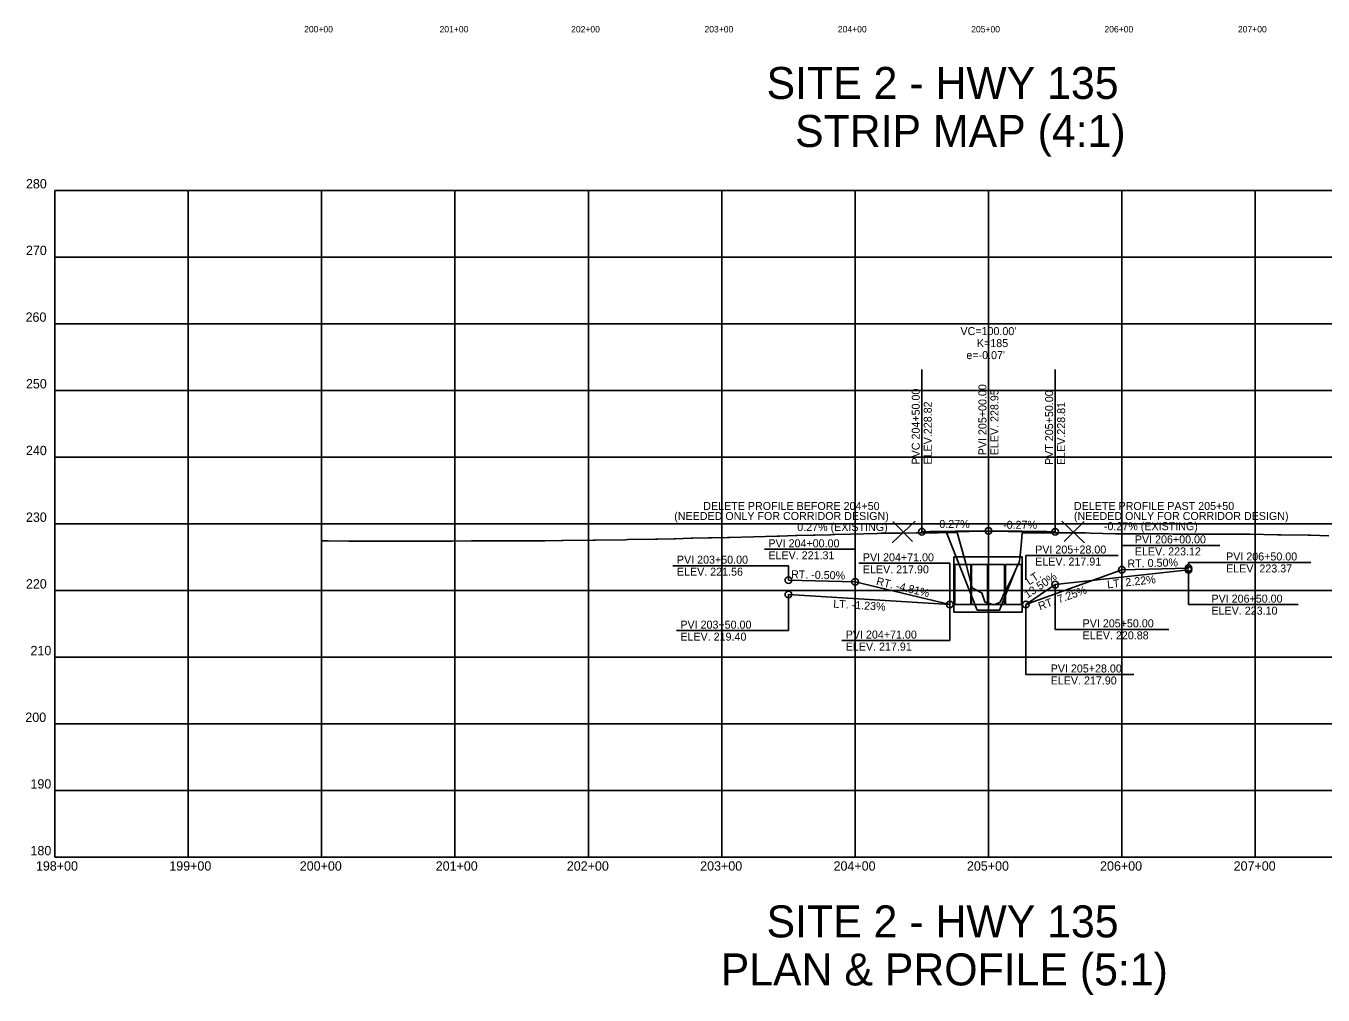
# Model space of a CAD drawing. Extents: x 1801553 to 1803097, y 521610 to 523048.
# Drawn here: x 1801553 to 1802526, y 521610 to 522336 of the extents above; entities that cross this region are included whole.
import ezdxf

# ---------------------------------------------------------------- set-up
doc = ezdxf.new("R2010")
doc.units = 0
for name, color, linetype in [('Default', 7, 'Continuous'), ('R_Axis', 7, 'Continuous'), ('R_Axis Annot', 7, 'Continuous'), ('R_Concrete', 7, 'Continuous'), ('R_Exist Surface', 7, 'Continuous'), ('R_Grid', 7, 'Continuous'), ('R_No Plot', 7, 'Continuous'), ('R_Vert Alg', 7, 'Continuous'), ('R_Vert Alg Annot', 7, 'Continuous')]:
    doc.layers.add(name, color=color, linetype=linetype)

msp = doc.modelspace()

# ---------------------------------------------------------------- linework, layer by layer
at = {"layer": 'R_Axis'}
for q in [(1801574.68, 522212.85), (1803074.68, 521712.85)]:
    msp.add_line((1801574.68, 521712.85), q, dxfattribs=at)
at = {"layer": 'R_Concrete'}
for p, q in [((1802248.83, 521938.21), (1802248.83, 521896.54)), ((1802248.83, 521938.21), (1802300, 521938.21)), ((1802249.42, 521932.37), (1802261.42, 521932.37)), ((1802249.42, 521932.37), (1802249.42, 521902.37)), ((1802261.42, 521932.37), (1802261.42, 521902.37)), ((1802262.08, 521932.37), (1802262.08, 521902.37)), ((1802262.08, 521932.37), (1802274.08, 521932.37)), ((1802274.08, 521932.37), (1802274.08, 521902.37)), ((1802274.75, 521932.37), (1802274.75, 521902.37)), ((1802274.75, 521932.37), (1802286.75, 521932.37)), ((1802286.75, 521932.37), (1802286.75, 521902.37)), ((1802287.42, 521932.37), (1802287.42, 521902.37)), ((1802287.42, 521932.37), (1802299.42, 521932.37)), ((1802299.42, 521932.37), (1802299.42, 521902.37)), ((1802300, 521938.21), (1802300, 521896.54)), ((1802261.42, 521902.37), (1802249.42, 521902.37)), ((1802274.08, 521902.37), (1802262.08, 521902.37)), ((1802286.75, 521902.37), (1802274.75, 521902.37)), ((1802299.42, 521902.37), (1802287.42, 521902.37)), ((1802300, 521896.54), (1802248.83, 521896.54))]:
    msp.add_line(p, q, dxfattribs=at)
at = {"layer": 'R_Exist Surface'}
msp.add_lwpolyline([(1801774.68, 521949.99), (1801779.53, 521949.99), (1801779.55, 521949.99), (1801795.04, 521949.94), (1801795.2, 521949.94), (1801795.36, 521949.94), (1801810.85, 521949.9), (1801811.16, 521949.9), (1801826.5, 521949.86), (1801826.96, 521949.86), (1801842.14, 521949.82), (1801842.73, 521949.82), (1801857.1, 521949.88), (1801857.73, 521949.88), (1801872.07, 521949.94), (1801872.73, 521949.94), (1801887.03, 521950), (1801887.73, 521950), (1801902, 521950.06), (1801902.65, 521950.06), (1801915.41, 521950.11), (1801916.11, 521950.11), (1801928.83, 521950.16), (1801929.57, 521950.17), (1801942.24, 521950.22), (1801954.83, 521950.27), (1801955.65, 521950.27), (1801978.39, 521950.61), (1801980.11, 521950.63), (1802002.64, 521950.97), (1802004.56, 521950.99), (1802025.05, 521951.38), (1802026.71, 521951.4), (1802038.77, 521951.69), (1802039.78, 521951.72), (1802051.81, 521952), (1802052.84, 521952.03), (1802064.84, 521952.31), (1802065.9, 521952.34), (1802066.97, 521952.37), (1802078.97, 521952.65), (1802080.66, 521952.69), (1802098.53, 521953.17), (1802116.39, 521953.64), (1802118.1, 521953.68), (1802130.1, 521954.01), (1802131.39, 521954.04), (1802143.23, 521954.37), (1802144.68, 521954.4), (1802156.37, 521954.72), (1802157.97, 521954.76), (1802159.59, 521954.8), (1802171.25, 521955.12), (1802191.24, 521955.66), (1802194.31, 521955.77), (1802206.52, 521955.9), (1802208.52, 521955.92), (1802220.57, 521956.05), (1802222.73, 521956.08), (1802234.62, 521956.2), (1802236.95, 521956.23), (1802248.67, 521956.35), (1802251.16, 521956.38), (1802258.17, 521931.27), (1802262.44, 521914.86), (1802268.58, 521911.7), (1802269.81, 521911.01), (1802272.01, 521904.44), (1802272.23, 521904.08), (1802277.68, 521902.34), (1802278.55, 521902.15), (1802279.41, 521902.43), (1802283.57, 521904.18), (1802285.34, 521907.84), (1802285.55, 521908.76), (1802287.93, 521913.25), (1802292.45, 521922.57), (1802296.87, 521932.49), (1802297.76, 521933.98), (1802298.18, 521936.95), (1802299.13, 521946.69), (1802300.08, 521956.13), (1802303.92, 521956.13), (1802323.8, 521956.07), (1802327.44, 521956.07), (1802347.53, 521956.02), (1802350.99, 521955.94), (1802369.84, 521955.41), (1802387.55, 521955.33), (1802391.57, 521955.32), (1802409.64, 521955.24), (1802413.16, 521955.22), (1802425.23, 521955.19), (1802428.49, 521955.16), (1802440.59, 521955.13), (1802452.86, 521955.1), (1802455.82, 521955.08), (1802468.11, 521955.05), (1802470.73, 521955.02), (1802491.31, 521954.71), (1802494, 521954.67), (1802514.51, 521954.37), (1802516.38, 521954.32), (1802529.8, 521953.97)], dxfattribs=at)
at = {"layer": 'R_Grid'}
for p, q in [((1801574.68, 522212.85), (1803074.68, 522212.85)), ((1801674.68, 521712.85), (1801674.68, 522212.85)), ((1801774.68, 521712.85), (1801774.68, 522212.85)), ((1801874.68, 521712.85), (1801874.68, 522212.85)), ((1801974.68, 521712.85), (1801974.68, 522212.85)), ((1802074.68, 521712.85), (1802074.68, 522212.85)), ((1802174.68, 521712.85), (1802174.68, 522212.85)), ((1802274.68, 521712.85), (1802274.68, 522212.85)), ((1802374.68, 521712.85), (1802374.68, 522212.85)), ((1802474.68, 521712.85), (1802474.68, 522212.85)), ((1801574.68, 522162.85), (1803074.68, 522162.85)), ((1801574.68, 522112.85), (1803074.68, 522112.85)), ((1801574.68, 522112.85), (1803074.68, 522112.85)), ((1801574.68, 522062.85), (1803074.68, 522062.85)), ((1801574.68, 522012.85), (1803074.68, 522012.85)), ((1801574.68, 521962.85), (1803074.68, 521962.85)), ((1801574.68, 521912.85), (1803074.68, 521912.85)), ((1801574.68, 521862.85), (1803074.68, 521862.85)), ((1801574.68, 521812.85), (1803074.68, 521812.85)), ((1801574.68, 521762.85), (1803074.68, 521762.85))]:
    msp.add_line(p, q, dxfattribs=at)
at = {"layer": 'R_No Plot'}
for p, q in [((1802219.65, 521964.89), (1802202.55, 521948.56)), ((1802202.98, 521964.64), (1802217.85, 521949.58)), ((1802329.71, 521964.89), (1802346.81, 521948.56)), ((1802346.38, 521964.64), (1802331.51, 521949.58))]:
    msp.add_line(p, q, dxfattribs=at)
msp.add_lwpolyline([(1802243.12, 521956.29), (1802266.35, 521898.21), (1802267.85, 521898.21), (1802281.51, 521898.21), (1802283.01, 521898.21), (1802295.46, 521929.33)], dxfattribs=at)
at = {"layer": 'R_Vert Alg'}
for p, q in [((1802249.68, 521957.26), (1802274.68, 521957.6)), ((1802274.68, 521957.6), (1802299.68, 521957.26)), ((1802124.68, 521920.66), (1802174.68, 521919.41)), ((1802302.68, 521902.35), (1802374.68, 521928.45)), ((1802324.68, 521917.25), (1802424.68, 521928.35)), ((1802374.68, 521928.45), (1802424.68, 521929.7)), ((1802174.68, 521919.41), (1802245.68, 521902.35)), ((1802302.68, 521902.4), (1802324.68, 521917.25)), ((1802124.68, 521909.82), (1802245.68, 521902.4))]:
    msp.add_line(p, q, dxfattribs=at)
msp.add_lwpolyline([(1802224.68, 521956.93), (1802226.76, 521956.96), (1802228.85, 521956.98), (1802230.93, 521957.01), (1802233.01, 521957.03), (1802235.1, 521957.05), (1802237.18, 521957.08), (1802239.26, 521957.1), (1802241.35, 521957.11), (1802243.43, 521957.13), (1802245.51, 521957.15), (1802247.6, 521957.16), (1802249.68, 521957.18), (1802251.76, 521957.19), (1802253.85, 521957.2), (1802255.93, 521957.22), (1802258.01, 521957.22), (1802260.1, 521957.23), (1802262.18, 521957.24), (1802264.26, 521957.25), (1802266.35, 521957.25), (1802268.43, 521957.26), (1802270.51, 521957.26), (1802272.6, 521957.26), (1802276.76, 521957.26), (1802278.85, 521957.26), (1802280.93, 521957.25), (1802283.01, 521957.25), (1802285.1, 521957.24), (1802287.18, 521957.24), (1802289.26, 521957.23), (1802291.35, 521957.22), (1802293.43, 521957.21), (1802295.51, 521957.2), (1802297.6, 521957.19), (1802299.68, 521957.17), (1802301.76, 521957.16), (1802303.85, 521957.14), (1802305.93, 521957.12), (1802308.01, 521957.11), (1802310.1, 521957.09), (1802312.18, 521957.07), (1802314.26, 521957.04), (1802316.35, 521957.02), (1802318.43, 521957), (1802320.51, 521956.97), (1802322.6, 521956.94), (1802324.68, 521956.92)], dxfattribs=at)
at = {"layer": 'R_Vert Alg Annot'}
for p, q in [((1802224.68, 522078.68), (1802224.68, 521956.93)), ((1802274.68, 521957.6), (1802274.68, 522078.68)), ((1802324.68, 522078.68), (1802324.68, 521956.92)), ((1802106.68, 521943.75), (1802174.68, 521943.75)), ((1802174.68, 521919.41), (1802174.68, 521943.75)), ((1802374.68, 521928.45), (1802374.68, 521946.68)), ((1802374.68, 521946.68), (1802448.09, 521946.68)), ((1802038.1, 521931.48), (1802124.68, 521931.48)), ((1802124.68, 521920.66), (1802124.68, 521931.48)), ((1802177.52, 521933.24), (1802245.68, 521933.24)), ((1802245.68, 521902.4), (1802245.68, 521933.24)), ((1802302.68, 521939.09), (1802372.05, 521939.09)), ((1802302.68, 521920.86), (1802302.68, 521939.09)), ((1802424.68, 521929.7), (1802424.68, 521933.89)), ((1802424.68, 521933.89), (1802516.5, 521933.89)), ((1802424.68, 521928.35), (1802424.68, 521902.27)), ((1802324.68, 521917.25), (1802324.68, 521883.75)), ((1802124.68, 521909.82), (1802124.68, 521882.77)), ((1802245.68, 521902.35), (1802245.68, 521875.34)), ((1802302.68, 521902.35), (1802302.68, 521849.91)), ((1802424.68, 521902.27), (1802506.97, 521902.27)), ((1802040.68, 521882.77), (1802124.68, 521882.77)), ((1802324.68, 521883.75), (1802410.01, 521883.75)), ((1802164.68, 521875.34), (1802245.68, 521875.34)), ((1802302.68, 521849.91), (1802383.68, 521849.91))]:
    msp.add_line(p, q, dxfattribs=at)
for centre in [(1802224.68, 521956.93), (1802274.68, 521957.6), (1802324.68, 521956.92), (1802374.68, 521928.45), (1802424.68, 521929.7), (1802424.68, 521929.7), (1802424.68, 521928.35), (1802424.68, 521928.35), (1802124.68, 521920.66), (1802124.68, 521920.66), (1802174.68, 521919.41), (1802124.68, 521909.82), (1802124.68, 521909.82), (1802324.68, 521917.25), (1802245.68, 521902.4), (1802245.68, 521902.35), (1802302.68, 521902.4), (1802302.68, 521902.35)]:
    msp.add_circle(centre, 2.5, dxfattribs=at)

# ---------------------------------------------------------------- texts
at = {"layer": 'Default'}
for s, p in [('SITE 2 - HWY 135', (1802108.31, 522281.41)), ('STRIP MAP (4:1)', (1802129.67, 522245.41)), ('SITE 2 - HWY 135', (1802108.31, 521652.78)), ('PLAN & PROFILE (5:1)', (1802073.92, 521616.78))]:
    msp.add_text(s, height=24, dxfattribs=at).set_placement(p)
at = {"layer": 'R_Axis Annot'}
for s, height, p in [('200+00', 4.8, (1801761.58, 522331.28)), ('201+00', 4.8, (1801863.13, 522331.28)), ('202+00', 4.8, (1801961.77, 522331.28)), ('203+00', 4.8, (1802061.77, 522331.28)), ('204+00', 4.8, (1802161.77, 522331.28)), ('205+00', 4.8, (1802261.77, 522331.28)), ('206+00', 4.8, (1802361.66, 522331.28)), ('207+00', 4.8, (1802461.77, 522331.28)), ('280', 7, (1801552.99, 522214.35)), ('270', 7, (1801552.99, 522164.35)), ('260', 7, (1801552.7, 522114.35)), ('260', 7, (1801552.7, 522114.35)), ('250', 7, (1801552.99, 522064.35)), ('240', 7, (1801552.99, 522014.35)), ('230', 7, (1801552.99, 521964.35)), ('220', 7, (1801552.99, 521914.35)), ('210', 7, (1801556.39, 521864.35)), ('200', 7, (1801552.52, 521814.35)), ('190', 7, (1801556.39, 521764.35)), ('180', 7, (1801556.39, 521714.35)), ('198+00', 7, (1801560.48, 521702.85)), ('-', 0.0001, (1801574.68, 521712.85)), ('199+00', 7, (1801660.48, 521702.85)), ('200+00', 7, (1801758.31, 521702.85)), ('201+00', 7, (1801860.25, 521702.85)), ('202+00', 7, (1801958.55, 521702.85)), ('203+00', 7, (1802058.55, 521702.85)), ('204+00', 7, (1802158.55, 521702.85)), ('205+00', 7, (1802258.55, 521702.85)), ('206+00', 7, (1802358.4, 521702.85)), ('207+00', 7, (1802458.55, 521702.85))]:
    msp.add_text(s, height=height, dxfattribs=at).set_placement(p)
at = {"layer": 'R_No Plot'}
for s, p in [('DELETE PROFILE BEFORE 204+50', (1802060.85, 521973.25)), ('DELETE PROFILE PAST 205+50', (1802338.79, 521973.25)), ('(NEEDED ONLY FOR CORRIDOR DESIGN)', (1802039.07, 521965.74)), ('(NEEDED ONLY FOR CORRIDOR DESIGN)', (1802338.79, 521965.74))]:
    msp.add_text(s, height=6, dxfattribs=at).set_placement(p)
at = {"layer": 'R_Vert Alg Annot'}
for s, p in [("VC=100.00'", (1802253.71, 522104.35)), ('K=185', (1802266.04, 522095.35)), ("e=-0.07'", (1802258.15, 522086.35)), ('0.27% (EXISTING)', (1802131.35, 521957.47)), ('0.27%', (1802237.87, 521959.76)), ('-0.27%', (1802285.71, 521959.11)), ('-0.27% (EXISTING)', (1802361.25, 521958.1)), ('PVI 204+00.00', (1802109.68, 521945.25)), ('PVI 206+00.00', (1802384.47, 521948.18)), ('ELEV. 221.31', (1802109.68, 521936.25)), ('PVI 204+71.00', (1802180.52, 521934.74)), ('PVI 205+28.00', (1802309.73, 521940.59)), ('ELEV. 223.12', (1802384.47, 521939.18)), ('PVI 206+50.00', (1802452.88, 521935.39)), ('PVI 203+50.00', (1802041.1, 521932.98)), ('ELEV. 221.56', (1802041.1, 521923.98)), ('ELEV. 217.90', (1802180.52, 521925.74)), ('ELEV. 217.91', (1802309.73, 521931.59)), ('ELEV. 223.37', (1802452.88, 521926.39)), ('PVI 206+50.00', (1802441.92, 521903.77)), ('ELEV. 223.10', (1802441.92, 521894.77)), ('PVI 205+50.00', (1802345.3, 521885.25)), ('PVI 203+50.00', (1802043.68, 521884.27)), ('ELEV. 219.40', (1802043.68, 521875.27)), ('PVI 204+71.00', (1802167.68, 521876.84)), ('ELEV. 220.88', (1802345.3, 521876.25)), ('ELEV. 217.91', (1802167.68, 521867.84)), ('PVI 205+28.00', (1802321.36, 521851.41)), ('ELEV. 217.90', (1802321.36, 521842.41))]:
    msp.add_text(s, height=6, dxfattribs=at).set_placement(p)
for s, rotation, p in [('PVI 205+00.00', 90, (1802273.18, 522014.24)), ('PVC 204+50.00', 90, (1802223.18, 522007.34)), ('ELEV. 228.95', 90, (1802282.18, 522014.24)), ('PVT 205+50.00', 90, (1802323.18, 522006.97)), ('ELEV.228.82', 90, (1802232.18, 522007.34)), ('ELEV.228.81', 90, (1802332.18, 522006.97)), ('RT. 0.50%', 1.4321, (1802378.98, 521930.06)), ('RT. -0.50%', 358.5679, (1802126.6, 521922.11)), ('RT. -4.81%', 346.48894, (1802190.16, 521917.23)), ('13.50%', 34.02563, (1802303.97, 521906.7)), ('LT.', 34.02563, (1802305.26, 521916.64)), ('LT. 2.22%', 6.33192, (1802363.99, 521914.41)), ('RT. 7.25%', 19.92558, (1802313.31, 521898.02)), ('LT. -1.23%', 356.4883, (1802158.19, 521900.06))]:
    msp.add_text(s, height=6, rotation=rotation, dxfattribs=at).set_placement(p)

doc.saveas('drawing.dxf')
